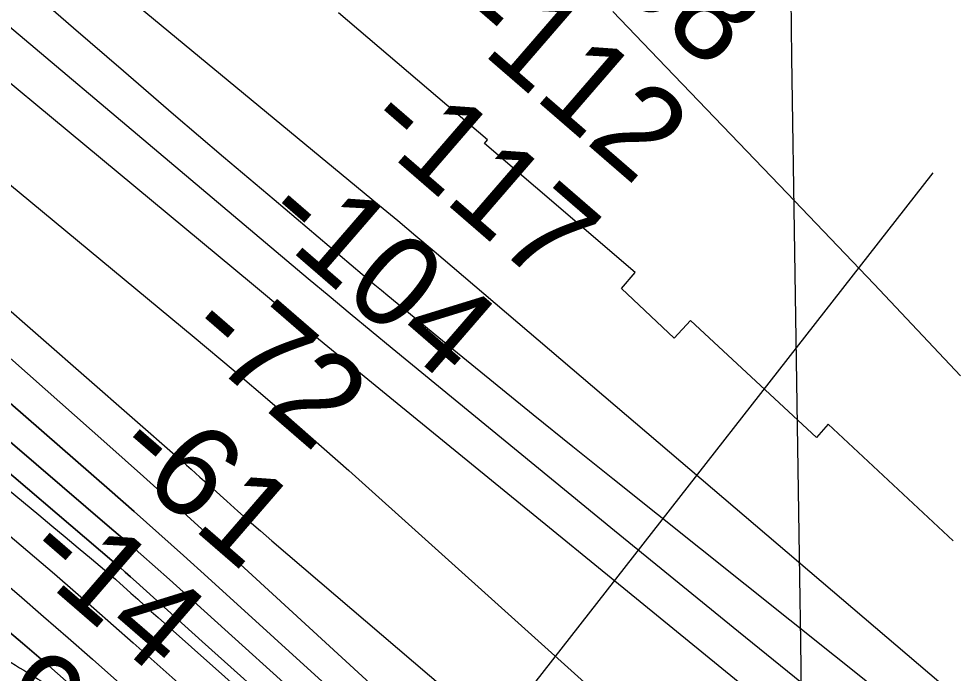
# Model space of a CAD drawing. Extents: x 3823584 to 3861785, y 301729 to 327625.
# Drawn here: x 3837614 to 3838296, y 324337 to 324815 of the extents above; entities that cross this region are included whole.
import ezdxf

# ---------------------------------------------------------------- set-up
doc = ezdxf.new("R2010")
doc.units = 0
for name, color, linetype in [('V-GRID-MAJR', 7, 'Continuous'), ('V-RIVR-EDGE', 7, 'Continuous'), ('V-RIVR-RANG', 7, 'Continuous'), ('V-RRAP-RVMT', 7, 'Continuous'), ('V-TOPO-DPTH', 7, 'Continuous'), ('V-TOPO-MAJR', 7, 'Continuous'), ('V-TOPO-MINR', 7, 'Continuous'), ('V-TOPO-WATR', 7, 'Continuous')]:
    doc.layers.add(name, color=color, linetype=linetype)

msp = doc.modelspace()

# ---------------------------------------------------------------- linework, layer by layer
at = {"layer": 'V-GRID-MAJR'}
msp.add_spline([(3838444.8910000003, 307319.343), (3838352.38, 313376.366), (3838259.823, 319436.473), (3838167.2660000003, 325496.576), (3838167.219, 325499.664)], degree=3, dxfattribs=at)
at = {"layer": 'V-RIVR-EDGE'}
msp.add_spline([(3836304.3756208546, 325474.18490968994), (3836346.414637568, 325438.3248399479), (3836389.407230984, 325406.0749957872), (3836417.6425015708, 325385.4333151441), (3836442.6682071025, 325366.7281829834), (3836470.247893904, 325340.94515767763), (3836497.8244014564, 325313.8763988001), (3836554.9028376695, 325258.4483785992), (3836598.5128638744, 325215.91107623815), (3836636.356164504, 325181.10248193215), (3836681.25510353, 325139.84773389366), (3836737.070060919, 325093.42302794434), (3836790.9421113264, 325041.2172897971), (3836840.3252216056, 324993.52274652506), (3836889.068644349, 324947.1155264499), (3836934.613629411, 324907.1449223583), (3836980.8110190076, 324871.0299293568), (3837015.471778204, 324849.0866188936), (3837040.494304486, 324829.09575316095), (3837085.3916538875, 324787.1981383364), (3837143.7621821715, 324734.3384060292), (3837181.60866205, 324700.815545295), (3837223.2932671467, 324659.5687453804), (3837272.052586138, 324619.5901931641), (3837314.3832372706, 324579.6275371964), (3837346.4455057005, 324546.7618498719), (3837364.398086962, 324527.4313367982), (3837395.83179523, 324500.35304017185), (3837442.024415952, 324462.30944681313), (3837492.7139249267, 324422.9689925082), (3837554.3051456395, 324372.67277922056), (3837573.562535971, 324361.05348832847), (3837583.2007688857, 324359.1010435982), (3837596.685075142, 324352.6389936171), (3837621.0774516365, 324337.7926517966), (3837648.0333471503, 324319.7256175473), (3837677.5368654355, 324292.00922300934), (3837718.5754244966, 324249.4782791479), (3837753.847257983, 324214.6760433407), (3837781.426944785, 324188.89301803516), (3837800.047826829, 324179.8467839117), (3837819.9544424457, 324170.79737053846), (3837850.7214395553, 324134.0776617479), (3837874.448694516, 324110.2327745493), (3837909.0728923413, 324073.5035280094), (3837941.7780275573, 324040.63625106), (3837989.872225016, 323991.65915346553), (3838022.5821291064, 323960.7204768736), (3838034.1219387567, 323947.83452790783), (3838046.301435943, 323933.66125574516), (3838066.8302532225, 323916.25298453), (3838089.9146413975, 323892.40968695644), (3838140.5946126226, 323849.2120319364), (3838186.144366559, 323811.1700282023), (3838215.652653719, 323785.38223402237), (3838265.675451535, 323736.40036755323), (3838297.1043909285, 323707.3934705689), (3838336.8747022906, 323671.9372406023), (3838359.952731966, 323645.5224758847), (3838385.6228939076, 323627.4586208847), (3838404.2374174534, 323615.8409196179), (3838421.5598489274, 323601.65493045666), (3838441.441030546, 323582.31964850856), (3838460.0476059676, 323567.48761331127), (3838468.395336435, 323563.60974747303), (3838484.446340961, 323555.21273863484), (3838548.5883636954, 323496.55289863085), (3838595.4381578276, 323464.2935167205), (3838649.9785090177, 323422.37205752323), (3838701.302936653, 323379.8156796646), (3838749.433695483, 323345.62451814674), (3838798.2232173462, 323317.86043486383), (3838856.617590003, 323274.6437043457), (3838932.9883882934, 323221.7394625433), (3838989.4684672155, 323184.31330197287), (3839037.599226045, 323150.12214045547), (3839068.4186807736, 323134.6170356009), (3839093.417362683, 323104.98316807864), (3839110.730256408, 323086.93997820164), (3839122.930418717, 323081.1239742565), (3839143.464004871, 323065.6443033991), (3839172.3405526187, 323044.35816634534), (3839190.955076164, 323032.7404650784), (3839215.98555057, 323015.9639332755), (3839242.319244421, 323006.25575686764), (3839316.801182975, 322969.42795358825), (3839341.8396055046, 322955.86575571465), (3839371.3828644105, 322944.2210308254), (3839391.2910696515, 322935.81448423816), (3839417.6104568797, 322920.32050675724), (3839461.26181333, 322894.4977408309), (3839483.709693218, 322873.22750002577), (3839520.2990527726, 322851.27942068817), (3839555.6010891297, 322828.6916538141), (3839599.9048501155, 322806.7244989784), (3839718.698497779, 322751.1438747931), (3839768.138834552, 322726.5925358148), (3839807.9457072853, 322705.9222419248), (3839836.8508682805, 322696.20770701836), (3839865.0988558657, 322680.7089606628), (3839887.567400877, 322667.7959880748), (3839924.172656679, 322652.2765765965), (3839969.7621512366, 322630.306242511), (3840004.4324481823, 322612.2201327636), (3840037.8249596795, 322597.35153619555), (3840085.3541819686, 322579.87650073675), (3840108.4624145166, 322565.6762049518), (3840121.9212867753, 322548.928286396), (3840123.184765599, 322539.92497214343), (3840122.5260025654, 322533.4978939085), (3840117.9957321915, 322521.29455234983), (3840112.8353120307, 322514.2357347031), (3840095.465191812, 322509.1357202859), (3840089.6793907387, 322509.1500269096), (3840085.168195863, 322504.661086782), (3840084.5094328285, 322498.2340085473), (3840085.779270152, 322491.8021614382), (3840130.719539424, 322467.2619498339), (3840169.888314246, 322448.52184592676), (3840197.5093312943, 322439.45335705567), (3840209.076164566, 322437.4961434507), (3840231.586039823, 322441.2977072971), (3840246.3910513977, 322448.9755473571), (3840266.343766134, 322458.5692707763), (3840273.434376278, 322466.26618633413), (3840278.590027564, 322471.3964036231), (3840288.898150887, 322480.37110462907), (3840295.9808129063, 322484.8536862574), (3840301.7666139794, 322484.8393796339), (3840308.195281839, 322484.8234833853), (3840320.395444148, 322479.00747944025), (3840324.873256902, 322469.99621706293), (3840326.781192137, 322461.6341799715), (3840338.324181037, 322450.0339645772), (3840344.7401318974, 322444.87513404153), (3840366.580116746, 322437.7495521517), (3840385.842275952, 322428.05886161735), (3840421.7967168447, 322409.3267058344), (3840466.0957089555, 322385.43095064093), (3840492.411916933, 322368.65123958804), (3840506.526372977, 322357.0446656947), (3840533.4854477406, 322340.2633650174), (3840559.1778644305, 322331.1996450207), (3840587.441748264, 322322.12956652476), (3840611.8452521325, 322311.78329220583), (3840642.0218400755, 322296.27977697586), (3840678.615968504, 322276.2602979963), (3840712.637040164, 322255.60431073), (3840733.1753951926, 322242.05324023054), (3840784.5268464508, 322210.42559773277), (3840835.889425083, 322183.29802273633), (3840892.388579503, 322153.5862635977), (3840923.854080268, 322139.3653026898), (3840950.8242824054, 322127.08406951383), (3840989.3295253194, 322099.98828701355), (3841017.5727440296, 322082.56094030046), (3841061.238407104, 322062.5239754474), (3841092.6943701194, 322044.4458138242), (3841151.0982805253, 322005.0862840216), (3841210.7847452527, 321964.43784139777), (3841240.294622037, 321939.29291400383), (3841299.971549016, 321894.78727066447), (3841335.8926077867, 321862.55491237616), (3841374.3692374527, 321823.88752772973), (3841411.5712609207, 321789.72338983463), (3841444.922442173, 321758.1402568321), (3841469.94019958, 321736.22079074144), (3841482.124465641, 321723.9761189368), (3841496.2198461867, 321704.6551436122), (3841509.051747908, 321694.3374825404), (3841523.1773313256, 321687.23097614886), (3841573.8986327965, 321660.747857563), (3841623.970708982, 321631.69486145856), (3841667.623655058, 321606.5149623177), (3841696.5208679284, 321593.58609348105), (3841738.2626995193, 321575.48249786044), (3841787.074476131, 321556.7185495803), (3841815.992354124, 321552.1469489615), (3841851.3325414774, 321544.9879849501), (3841886.661601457, 321533.32895343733), (3841930.322495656, 321511.36338822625), (3841950.219573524, 321498.4567741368), (3841977.1818275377, 321482.9612070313), (3841998.380535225, 321476.4800815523), (3842052.9924195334, 321463.4876277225), (3842082.546805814, 321456.3429703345), (3842109.5185975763, 321444.7046039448), (3842146.1190845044, 321427.2565921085), (3842196.2006984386, 321402.06079671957), (3842241.1346092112, 321374.94911797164), (3842288.6336286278, 321345.2596135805), (3842321.375325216, 321327.17827270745), (3842366.940975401, 321295.56493683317), (3842395.188962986, 321280.06619047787), (3842429.2227516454, 321264.5531374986), (3842452.3516493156, 321258.7101099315), (3842470.9725313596, 321249.663875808)], degree=3, dxfattribs=at)
at = {"layer": 'V-RIVR-RANG'}
msp.add_line((3837739.7829, 324009.6034000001), (3838281.0541, 324702.183), dxfattribs=at)
at = {"layer": 'V-RRAP-RVMT'}
for p, q in [((3837956.147000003, 324726.20000000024), (3837847.5850000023, 324818.9770000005)), ((3837953.863000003, 324723.53500000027), (3837956.147000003, 324726.20000000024)), ((3838063.7040000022, 324629.6320000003), (3837953.863000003, 324723.53500000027)), ((3838053.7125558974, 324617.94559691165), (3838063.7040000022, 324629.6320000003)), ((3838092.185000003, 324581.79800000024), (3838053.7125558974, 324617.94559691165)), ((3838104.148000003, 324594.728), (3838092.185000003, 324581.79800000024)), ((3838195.986000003, 324509.4410000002), (3838104.148000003, 324594.728)), ((3838204.500000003, 324519.03200000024), (3838195.986000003, 324509.4410000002)), ((3838295.732000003, 324433.9030000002), (3838204.500000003, 324519.03200000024))]:
    msp.add_line(p, q, dxfattribs=at)
at = {"layer": 'V-TOPO-DPTH'}
for points in [[(3838382.7371031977, 323805.5230493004), (3837860.9331754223, 324260.5584050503), (3837832.560879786, 324285.4311535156), (3837804.275892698, 324310.4022774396), (3837776.121868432, 324335.5209645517), (3837748.0551527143, 324360.7380271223), (3837699.881196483, 324404.2489813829), (3837695.951561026, 324407.76680775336), (3837692.0014180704, 324411.2612445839), (3837688.0205138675, 324414.7205971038), (3837684.0191021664, 324418.1565600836), (3837578.9735416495, 324507.55360117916), (3837522.3488812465, 324555.5693497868), (3837465.6107774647, 324603.45018290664), (3837408.7025086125, 324651.1286427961), (3837351.6807963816, 324698.6721871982), (3836968.178114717, 325017.27296973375)], [(3838382.7371031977, 323805.5230493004), (3837860.9331754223, 324260.5584050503), (3837832.560879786, 324285.4311535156), (3837804.275892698, 324310.4022774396), (3837776.121868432, 324335.5209645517), (3837748.0551527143, 324360.7380271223), (3837699.881196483, 324404.2489813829), (3837695.951561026, 324407.76680775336), (3837692.0014180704, 324411.2612445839), (3837688.0205138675, 324414.7205971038), (3837684.0191021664, 324418.1565600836), (3837578.9735416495, 324507.55360117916), (3837522.3488812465, 324555.5693497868), (3837465.6107774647, 324603.45018290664), (3837408.7025086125, 324651.1286427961), (3837351.6807963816, 324698.6721871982), (3836968.178114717, 325017.27296973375)], [(3837056.1566609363, 324980.11414428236), (3837682.266621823, 324442.6266671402), (3837692.828370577, 324433.4915615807), (3837703.34445806, 324424.30457873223), (3837713.792053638, 324415.0397799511), (3837724.193987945, 324405.7231038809), (3837852.762363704, 324289.7055937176), (3837927.587822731, 324222.53700258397), (3838002.6447168, 324155.6293990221), (3838078.048763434, 324089.11327681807), (3838153.6842451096, 324022.8581421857), (3838401.160738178, 323807.2092183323)], [(3838401.160738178, 323807.2092183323), (3838153.6842451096, 324022.8581421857), (3838078.048763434, 324089.11327681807), (3838002.6447168, 324155.6293990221), (3837927.587822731, 324222.53700258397), (3837852.762363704, 324289.7055937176), (3837724.193987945, 324405.7231038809), (3837713.792053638, 324415.0397799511), (3837703.34445806, 324424.30457873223), (3837692.828370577, 324433.4915615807), (3837682.266621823, 324442.6266671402), (3837056.1566609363, 324980.11414428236)], [(3836971.9178616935, 324972.83050933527), (3837252.283767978, 324737.8850834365), (3837322.0034214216, 324679.353446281), (3837391.652678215, 324620.7383131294), (3837461.196340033, 324561.99793598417), (3837530.6696052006, 324503.1740628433), (3837611.3959127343, 324434.6972930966), (3837640.340531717, 324409.9202919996), (3837669.1349194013, 324384.971469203), (3837697.7039601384, 324359.76491385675), (3837726.122769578, 324334.38653681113), (3838066.8243204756, 324027.3728192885), (3838119.971225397, 323979.69030236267), (3838173.255810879, 323932.1628219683), (3838226.746917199, 323884.8678963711), (3838280.3757040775, 323837.7280073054), (3838339.2406858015, 323786.21231701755)], [(3836971.9178616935, 324972.83050933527), (3837252.283767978, 324737.8850834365), (3837322.0034214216, 324679.353446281), (3837391.652678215, 324620.7383131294), (3837461.196340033, 324561.99793598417), (3837530.6696052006, 324503.1740628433), (3837611.3959127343, 324434.6972930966), (3837640.340531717, 324409.9202919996), (3837669.1349194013, 324384.971469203), (3837697.7039601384, 324359.76491385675), (3837726.122769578, 324334.38653681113), (3838066.8243204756, 324027.3728192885), (3838119.971225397, 323979.69030236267), (3838173.255810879, 323932.1628219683), (3838226.746917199, 323884.8678963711), (3838280.3757040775, 323837.7280073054), (3838339.2406858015, 323786.21231701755)], [(3838324.934771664, 323727.84568335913), (3838008.706183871, 324009.45784384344), (3837946.1737909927, 324065.22076796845), (3837883.691674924, 324121.0398939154), (3837821.284974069, 324176.94332259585), (3837758.928550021, 324232.9029530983), (3837651.055469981, 324329.84148260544), (3837642.64045044, 324337.3363473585), (3837634.181647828, 324344.78101785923), (3837625.657170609, 324352.1503969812), (3837617.0889103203, 324359.46958185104), (3837330.422620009, 324602.1558655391), (3837256.6802777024, 324663.8755040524), (3837182.482062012, 324725.03570046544), (3837107.600036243, 324785.35673372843), (3837032.2621370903, 324845.1183248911)], [(3837280.896661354, 324819.57523911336), (3837341.037718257, 324767.2090035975), (3837680.44013835, 324471.27772652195), (3837698.520803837, 324455.4131762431), (3837716.5348538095, 324439.4738118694), (3837734.448980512, 324423.42222635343), (3837752.2964916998, 324407.29582674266), (3838090.8038121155, 324099.50619266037), (3838147.0098765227, 324048.7305498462), (3838203.4323590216, 323998.19812391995), (3838260.179468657, 323948.0305233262), (3838317.142996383, 323898.1061396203)], [(3838317.142996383, 323898.1061396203), (3838260.179468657, 323948.0305233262), (3838203.4323590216, 323998.19812391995), (3838147.0098765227, 324048.7305498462), (3838090.8038121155, 324099.50619266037), (3837752.2964916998, 324407.29582674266), (3837734.448980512, 324423.42222635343), (3837716.5348538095, 324439.4738118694), (3837698.520803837, 324455.4131762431), (3837680.44013835, 324471.27772652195), (3837341.037718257, 324767.2090035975), (3837280.896661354, 324819.57523911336)]]:
    msp.add_lwpolyline(points, dxfattribs=at)
at = {"layer": 'V-TOPO-MAJR'}
for points in [[(3837162.0284859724, 325235.5557839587), (3837654.2222439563, 324807.99318984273), (3837690.636681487, 324776.4931891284), (3837727.138057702, 324745.0946829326), (3837763.769841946, 324713.8484185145), (3837800.488564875, 324682.70364861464), (3837864.7981161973, 324628.38615981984), (3837869.434867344, 324624.485373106), (3837874.081747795, 324620.5967390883), (3837878.7438222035, 324616.7263341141), (3837883.416025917, 324612.868081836), (3837931.607885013, 324573.2302659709), (3837960.435159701, 324549.62583231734), (3837989.331156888, 324526.10621048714), (3838018.330237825, 324502.7138063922), (3838047.3980412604, 324479.40621412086), (3838595.016252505, 324042.28010728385)], [(3837034.082676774, 325068.74782989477), (3837365.448528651, 324780.444643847), (3837426.81625158, 324726.8929923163), (3837488.0784204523, 324673.2212163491), (3837549.1822582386, 324619.36925372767), (3837610.180541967, 324565.39716667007), (3837678.577766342, 324504.6985976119), (3837705.237636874, 324480.91852666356), (3837731.816667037, 324457.04889665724), (3837758.2744366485, 324433.0449280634), (3837784.6513658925, 324408.95140041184), (3838390.4718885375, 323852.75425090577)]]:
    msp.add_lwpolyline(points, dxfattribs=at)
at = {"layer": 'V-TOPO-MINR'}
for points in [[(3837031.0592715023, 325107.31151023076), (3837730.3058873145, 324494.8511441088), (3837733.555459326, 324491.99589468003), (3837736.7990519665, 324489.1338899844), (3837740.0336755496, 324486.2617523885), (3837743.2623197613, 324483.38285952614), (3837746.48518188, 324480.49745394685), (3837749.706314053, 324477.6101201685), (3837752.924851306, 324474.71989409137), (3837756.14165861, 324471.8277398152), (3837765.989190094, 324462.9660591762), (3837774.1564923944, 324455.6735855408), (3837782.3611584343, 324448.4237287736), (3837790.6218700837, 324441.23779730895), (3837798.919945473, 324434.0944827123), (3838443.612482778, 323883.46075332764)], [(3836968.178114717, 325017.27296973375), (3837351.6807963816, 324698.6721871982), (3837408.7025086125, 324651.1286427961), (3837465.6107774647, 324603.45018290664), (3837522.3488812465, 324555.5693497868), (3837578.9735416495, 324507.55360117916), (3837684.0191021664, 324418.1565600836), (3837688.0205138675, 324414.7205971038), (3837692.0014180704, 324411.2612445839), (3837695.951561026, 324407.76680775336), (3837699.881196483, 324404.2489813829), (3837748.0551527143, 324360.7380271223), (3837776.121868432, 324335.5209645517), (3837804.275892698, 324310.4022774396), (3837832.560879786, 324285.4311535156), (3837860.9331754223, 324260.5584050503), (3838382.7371031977, 323805.5230493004)], [(3837481.950768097, 325005.11038280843), (3837877.345378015, 324678.4476030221), (3837890.657541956, 324667.3973671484), (3837903.93525298, 324656.306080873), (3837917.1612846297, 324645.1532189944), (3837930.3528633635, 324633.95930671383), (3838491.4475403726, 324155.5873045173)], [(3836970.0586820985, 324997.1175565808), (3837628.9950841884, 324452.9762194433), (3837638.6086303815, 324445.0056336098), (3837648.201167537, 324437.00994346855), (3837657.7621911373, 324428.97659686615), (3837667.3022057, 324420.91814595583), (3837684.932040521, 324405.96673235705), (3837685.638491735, 324405.3618598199), (3837687.7308906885, 324403.5164530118), (3837696.1927654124, 324395.8702342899), (3837701.1188868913, 324391.4292447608), (3837706.0518067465, 324386.9958371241), (3837710.9949241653, 324382.57380232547), (3837715.944839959, 324378.15934941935), (3838361.295295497, 323803.9532928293)], [(3837056.1566609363, 324980.11414428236), (3837682.266621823, 324442.6266671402), (3837692.828370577, 324433.4915615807), (3837703.34445806, 324424.30457873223), (3837713.792053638, 324415.0397799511), (3837724.193987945, 324405.7231038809), (3837852.762363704, 324289.7055937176), (3837927.587822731, 324222.53700258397), (3838002.6447168, 324155.6293990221), (3838078.048763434, 324089.11327681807), (3838153.6842451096, 324022.8581421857), (3838401.160738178, 323807.2092183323)], [(3836971.9178616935, 324972.83050933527), (3837252.283767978, 324737.8850834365), (3837322.0034214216, 324679.353446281), (3837391.652678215, 324620.7383131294), (3837461.196340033, 324561.99793598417), (3837530.6696052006, 324503.1740628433), (3837611.3959127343, 324434.6972930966), (3837640.340531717, 324409.9202919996), (3837669.1349194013, 324384.971469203), (3837697.7039601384, 324359.76491385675), (3837726.122769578, 324334.38653681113), (3838066.8243204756, 324027.3728192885), (3838119.971225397, 323979.69030236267), (3838173.255810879, 323932.1628219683), (3838226.746917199, 323884.8678963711), (3838280.3757040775, 323837.7280073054), (3838339.2406858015, 323786.21231701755)], [(3837493.8295527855, 324904.87131374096), (3837825.3862104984, 324625.32975199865), (3837840.646179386, 324612.5163905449), (3837855.94043411, 324599.7442541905), (3837871.286117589, 324587.03395548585), (3837886.666086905, 324574.3648818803), (3838048.695632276, 324441.4428904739), (3838139.04726298, 324367.8310016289), (3838229.726863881, 324294.62820088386), (3838320.8984200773, 324222.0390322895)], [(3837456.399953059, 324893.7337863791), (3837784.022575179, 324621.75419923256), (3837810.490876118, 324599.83810391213), (3837836.996246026, 324577.96704888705), (3837863.557219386, 324556.1635543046), (3837890.1552617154, 324534.4051000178), (3838405.9206212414, 324113.57960920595)], [(3837429.4920666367, 324840.6567201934), (3837522.2009164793, 324764.45603703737), (3837614.7576947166, 324688.0697707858), (3837742.2566300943, 324582.524261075), (3837770.801000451, 324558.5989954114), (3837799.1469274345, 324534.44372406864), (3837827.1951893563, 324509.94344420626), (3837855.0450079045, 324485.21315866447), (3838213.317257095, 324163.130163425), (3838262.70123192, 324118.8504552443), (3838312.161710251, 324074.65659193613)], [(3837123.035889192, 324815.42369030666), (3837165.697822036, 324778.91920664), (3837614.615881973, 324394.3863041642), (3837632.534403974, 324378.9380260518), (3837650.386447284, 324363.4137931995), (3837668.1387725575, 324347.775628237), (3837685.824619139, 324332.06150853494), (3838107.247108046, 323955.20173551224), (3838151.018769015, 323916.2039689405), (3838194.8860438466, 323877.3144568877), (3838238.896739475, 323838.58732661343), (3838283.0030489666, 323799.96845085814), (3838362.0912485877, 323730.97767757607)], [(3837280.896661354, 324819.57523911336), (3837341.037718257, 324767.2090035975), (3837680.44013835, 324471.27772652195), (3837698.520803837, 324455.4131762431), (3837716.5348538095, 324439.4738118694), (3837734.448980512, 324423.42222635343), (3837752.2964916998, 324407.29582674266), (3838090.8038121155, 324099.50619266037), (3838147.0098765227, 324048.7305498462), (3838203.4323590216, 323998.19812391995), (3838260.179468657, 323948.0305233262), (3838317.142996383, 323898.1061396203)], [(3838301.043084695, 324554.3322431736), (3838237.9214188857, 324620.9902983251), (3838174.5505301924, 324687.4136710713), (3838080.615746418, 324785.3234229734), (3838064.025981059, 324802.6165303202), (3838047.437098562, 324819.9104844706)]]:
    msp.add_lwpolyline(points, dxfattribs=at)
at = {"layer": 'V-TOPO-WATR'}
msp.add_lwpolyline([(3837032.2621370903, 324845.1183248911), (3837107.600036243, 324785.35673372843), (3837182.482062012, 324725.03570046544), (3837256.6802777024, 324663.8755040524), (3837330.422620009, 324602.1558655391), (3837617.0889103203, 324359.46958185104), (3837625.657170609, 324352.1503969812), (3837634.181647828, 324344.78101785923), (3837642.64045044, 324337.3363473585), (3837651.055469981, 324329.84148260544), (3837758.928550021, 324232.9029530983), (3837821.284974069, 324176.94332259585), (3837883.691674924, 324121.0398939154), (3837946.1737909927, 324065.22076796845), (3838008.706183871, 324009.45784384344), (3838324.934771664, 323727.84568335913)], dxfattribs=at)

# ---------------------------------------------------------------- texts
at = {"layer": 'V-RIVR-RANG'}
for s, height, rotation, p in [('-108', 67.00000000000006, 319.12536111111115, (3837984.9631026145, 324893.0546448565)), ('-112', 67.00000000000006, 319.12536111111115, (3837928.909947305, 324809.3159350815)), ('-117', 67.00000000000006, 319.12536111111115, (3837863.282947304, 324733.86393508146)), ('-104', 67.00000000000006, 319.12536111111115, (3837788.6794679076, 324666.17978799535)), ('-72', 67.00000000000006, 319.12536111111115, (3837732.825767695, 324582.2684592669)), ('-61', 67.00000000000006, 319.12536111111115, (3837680.1633490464, 324495.59622728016)), ('-14', 67.00000000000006, 319.12536111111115, (3837614.5353490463, 324420.14422728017)), ('4.9', 67, 318.8383257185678, (3837532.9077246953, 324359.10754468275))]:
    msp.add_text(s, height=height, rotation=rotation, dxfattribs=at).set_placement(p)

doc.saveas('drawing.dxf')
